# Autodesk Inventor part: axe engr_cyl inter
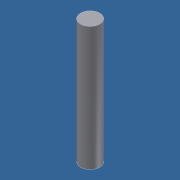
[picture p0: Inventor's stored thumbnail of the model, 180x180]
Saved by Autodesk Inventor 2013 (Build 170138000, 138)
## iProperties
Created: 2011-07
Part Number: axe engr_cyl inter
Document SubType Name: Modeling
Designer: Laur
Density: 7.85 g/cm^3
Material: Acier allié
Mass: 0.036649 g
Surface Area: 0.209004 cm^2
Volume: 0.00466866 cm^3
Author: Laur
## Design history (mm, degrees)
sketch "Esquisse1"
  geometry: C1 r 0.5 at (0, 0); 1 further point
  constraints: 1 centre point, 1 coincident
  dimensions: "d0" = 1 diameter of C1
extrude "axe" new body sketch "Esquisse1" distance "d1" = 6.45; taper "d2" = 0 deg
node "Solide1"
node "Corps solides"
node "Corps surfaciques"
